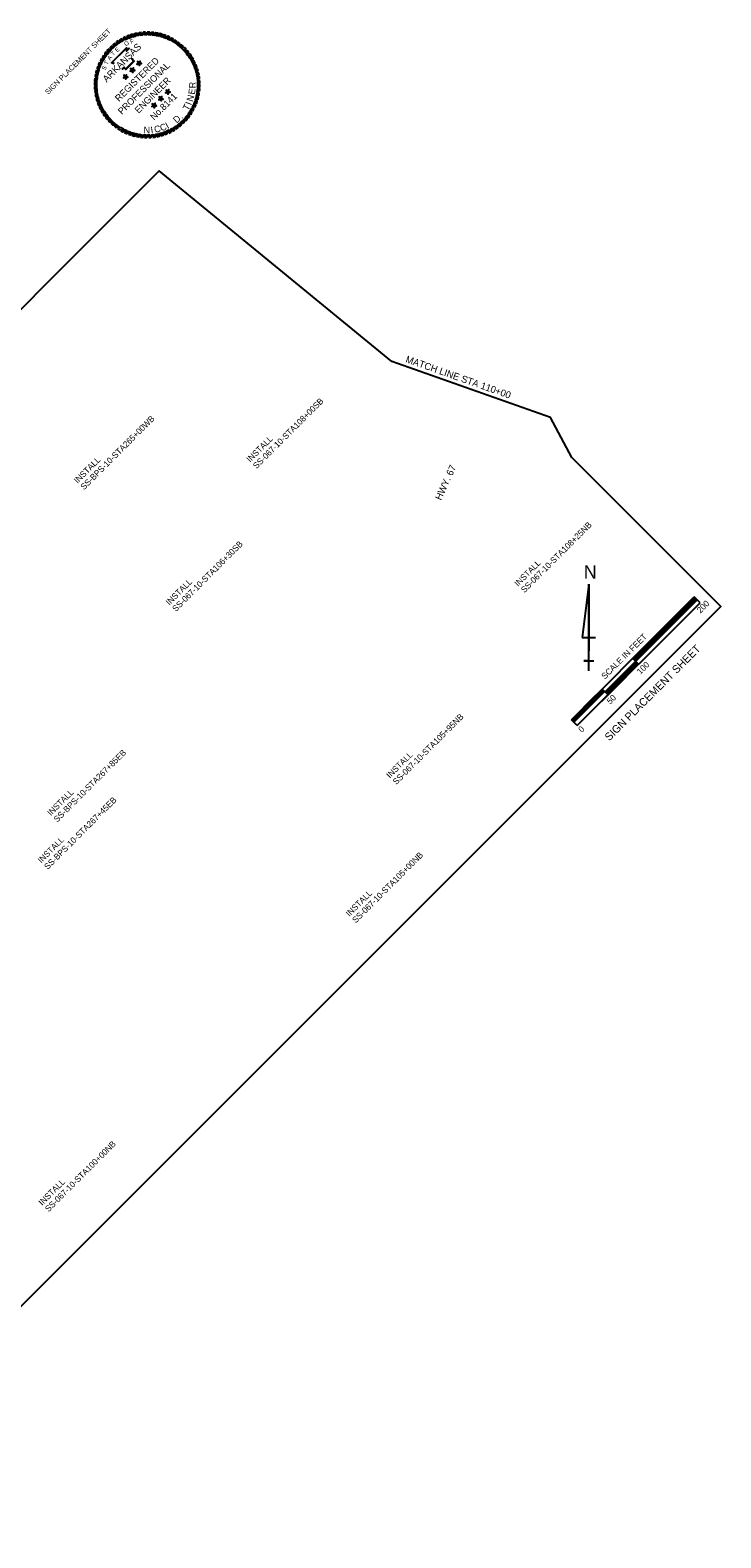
# Model space of a CAD drawing. Extents: x 991038 to 994490, y 1838525 to 1841963.
# Drawn here: x 991998 to 992794, y 1838525 to 1840263 of the extents above; entities that cross this region are included whole.
import ezdxf

# ---------------------------------------------------------------- set-up
doc = ezdxf.new("R2010")
doc.units = 0
for name, color, linetype in [('5', 7, 'Continuous'), ('63', 7, 'Continuous'), ('G-ANNO-SYMB', 7, 'Continuous'), ('G-ANNO-TEXT', 7, 'Continuous'), ('Level 10', 7, 'Continuous'), ('Plan Notes', 7, 'Continuous'), ('R_Annotation', 7, 'Continuous'), ('R_No Plot', 7, 'Continuous')]:
    doc.layers.add(name, color=color, linetype=linetype)

msp = doc.modelspace()

# ---------------------------------------------------------------- linework, layer by layer
at = {"layer": '5'}
msp.add_line((992597.4, 1839816.5), (992414.5, 1839881), dxfattribs=at)
at = {"layer": '63'}
for p, q in [((992641.6, 1839624.4), (992633.9, 1839562.9)), ((992641.6, 1839524.4), (992641.6, 1839624.4)), ((992641.6, 1839624.4), (992641.6, 1839547.5)), ((992633.9, 1839562.9), (992649.2, 1839562.9)), ((992641.6, 1839535.9), (992635.8, 1839535.9)), ((992635.8, 1839535.9), (992647.3, 1839535.9)), ((992641.6, 1839524.4), (992641.6, 1839547.5)), ((992641.6, 1839524.4), (992641.6, 1839535.9))]:
    msp.add_line(p, q, dxfattribs=at)
at = {"layer": 'G-ANNO-SYMB'}
for points in [[(992095.6, 1840247.9), (992093.6, 1840246.3), (992092.7, 1840241.7), (992094.8, 1840243.6)], [(992099.5, 1840250.7), (992097.4, 1840249.2), (992096.1, 1840244.7), (992098.3, 1840246.4)], [(992103.6, 1840253.1), (992101.4, 1840251.8), (992099.7, 1840247.4), (992102.1, 1840249)], [(992107.9, 1840255.2), (992105.5, 1840254.1), (992103.6, 1840249.9), (992106, 1840251.3)], [(992112.3, 1840257), (992109.9, 1840256.1), (992107.6, 1840252), (992110.2, 1840253.2)], [(992116.9, 1840258.4), (992114.4, 1840257.7), (992111.8, 1840253.8), (992114.4, 1840254.8)], [(992121.5, 1840259.5), (992119, 1840259), (992116.1, 1840255.3), (992118.8, 1840256.1)], [(992126.3, 1840260.2), (992123.7, 1840259.9), (992120.5, 1840256.5), (992123.3, 1840257)], [(992131, 1840260.5), (992128.4, 1840260.4), (992125, 1840257.2), (992127.8, 1840257.6)], [(992135.8, 1840260.5), (992133.2, 1840260.5), (992129.5, 1840257.7), (992132.3, 1840257.8)], [(992140.6, 1840260), (992138, 1840260.3), (992134.1, 1840257.8), (992136.9, 1840257.6)], [(992145.3, 1840259.3), (992142.7, 1840259.7), (992138.6, 1840257.5), (992141.4, 1840257.1)], [(992149.9, 1840258.1), (992147.4, 1840258.8), (992143.1, 1840256.8), (992145.9, 1840256.3)], [(992154.4, 1840256.6), (992151.9, 1840257.4), (992147.6, 1840255.8), (992150.3, 1840255.1)], [(992158.8, 1840254.7), (992156.4, 1840255.8), (992151.9, 1840254.5), (992154.6, 1840253.5)], [(992163, 1840252.5), (992160.7, 1840253.7), (992156.2, 1840252.8), (992158.7, 1840251.6)], [(992167.1, 1840249.9), (992164.9, 1840251.4), (992160.3, 1840250.8), (992162.7, 1840249.4)], [(992170.9, 1840247.1), (992168.8, 1840248.7), (992164.2, 1840248.5), (992166.5, 1840246.9)], [(992174.5, 1840244), (992172.6, 1840245.7), (992167.9, 1840245.9), (992170.1, 1840244.1)], [(992080, 1840230), (992078.8, 1840227.7), (992079.7, 1840223.2), (992080.9, 1840225.7)], [(992082.6, 1840234.1), (992081.1, 1840231.9), (992081.7, 1840227.3), (992083.1, 1840229.7)], [(992085.4, 1840237.9), (992083.8, 1840235.8), (992084, 1840231.2), (992085.6, 1840233.5)], [(992088.6, 1840241.5), (992086.8, 1840239.6), (992086.6, 1840234.9), (992088.4, 1840237.1)], [(992092, 1840244.8), (992090.1, 1840243), (992089.5, 1840238.4), (992091.4, 1840240.5)], [(992177.8, 1840240.5), (992176, 1840242.4), (992171.4, 1840243), (992173.5, 1840241.1)], [(992180.9, 1840236.9), (992179.3, 1840238.9), (992174.7, 1840239.8), (992176.6, 1840237.8)], [(992183.7, 1840233), (992182.2, 1840235.1), (992177.7, 1840236.4), (992179.4, 1840234.2)], [(992186.1, 1840228.9), (992184.8, 1840231.2), (992180.4, 1840232.8), (992182, 1840230.4)], [(992188.2, 1840224.6), (992187.1, 1840227), (992182.9, 1840228.9), (992184.3, 1840226.5)], [(992073.3, 1840212.3), (992072.8, 1840209.7), (992075, 1840205.6), (992075.4, 1840208.4)], [(992074.4, 1840216.9), (992073.7, 1840214.4), (992075.7, 1840210.1), (992076.3, 1840212.9)], [(992076, 1840221.4), (992075.1, 1840218.9), (992076.7, 1840214.6), (992077.5, 1840217.3)], [(992077.8, 1840225.8), (992076.8, 1840223.4), (992078, 1840218.9), (992079, 1840221.6)], [(992107.8, 1840209), (992107.6, 1840210.1), (992105.8, 1840211), (992106.7, 1840209.2)], [(992107.8, 1840209), (992108.7, 1840209.5), (992109, 1840211.5), (992107.6, 1840210.1)], [(992115.6, 1840216.9), (992114.6, 1840217), (992113.2, 1840215.6), (992115.2, 1840215.9)], [(992115.6, 1840216.9), (992115.5, 1840217.9), (992113.7, 1840218.8), (992114.6, 1840217)], [(992115.6, 1840216.9), (992115.2, 1840215.9), (992116.1, 1840214.1), (992116.4, 1840216.1)], [(992115.6, 1840216.9), (992116.6, 1840217.4), (992116.9, 1840219.4), (992115.5, 1840217.9)], [(992115.6, 1840216.9), (992116.4, 1840216.1), (992118.4, 1840216.4), (992116.6, 1840217.4)], [(992123.5, 1840224.7), (992122.5, 1840224.9), (992121, 1840223.5), (992123, 1840223.8)], [(992123.5, 1840224.7), (992123.3, 1840225.8), (992121.5, 1840226.7), (992122.5, 1840224.9)], [(992123.5, 1840224.7), (992123, 1840223.8), (992123.9, 1840222), (992124.3, 1840224)], [(992123.5, 1840224.7), (992124.4, 1840225.2), (992124.8, 1840227.2), (992123.3, 1840225.8)], [(992123.5, 1840224.7), (992124.3, 1840224), (992126.2, 1840224.3), (992124.4, 1840225.2)], [(992190, 1840220.2), (992189.1, 1840222.6), (992185, 1840224.9), (992186.2, 1840222.4)], [(992191.4, 1840215.6), (992190.7, 1840218.1), (992186.8, 1840220.7), (992187.8, 1840218.1)], [(992192.5, 1840211), (992192, 1840213.5), (992188.3, 1840216.4), (992189.1, 1840213.7)], [(992193.2, 1840206.3), (992192.9, 1840208.9), (992189.5, 1840212), (992190, 1840209.3)], [(992072, 1840202.8), (992072, 1840200.2), (992074.8, 1840196.5), (992074.7, 1840199.3)], [(992072, 1840198), (992072.1, 1840195.4), (992075.3, 1840192), (992075, 1840194.8)], [(992072.5, 1840207.5), (992072.2, 1840204.9), (992074.8, 1840201.1), (992074.9, 1840203.9)], [(992072.3, 1840193.3), (992072.7, 1840190.7), (992076.1, 1840187.5), (992075.5, 1840190.3)], [(992107.8, 1840209), (992106.7, 1840209.2), (992105.3, 1840207.8), (992107.3, 1840208.1)], [(992107.8, 1840209), (992107.3, 1840208.1), (992108.2, 1840206.3), (992108.5, 1840208.3)], [(992107.8, 1840209), (992108.5, 1840208.3), (992110.5, 1840208.6), (992108.7, 1840209.5)], [(992156.4, 1840191.8), (992156.3, 1840192.9), (992154.5, 1840193.8), (992155.4, 1840192)], [(992156.4, 1840191.8), (992157.4, 1840192.3), (992157.7, 1840194.3), (992156.3, 1840192.9)], [(992192.3, 1840187.3), (992192.7, 1840189.8), (992190.5, 1840193.9), (992190.1, 1840191.1)], [(992193.5, 1840201.5), (992193.4, 1840204.1), (992190.2, 1840207.5), (992190.6, 1840204.7)], [(992193.1, 1840192), (992193.3, 1840194.6), (992190.8, 1840198.5), (992190.6, 1840195.6)], [(992193.5, 1840196.7), (992193.6, 1840199.3), (992190.7, 1840203), (992190.8, 1840200.2)], [(992073, 1840188.5), (992073.6, 1840186), (992077.2, 1840183.1), (992076.5, 1840185.8)], [(992074.1, 1840183.9), (992074.8, 1840181.4), (992078.7, 1840178.8), (992077.7, 1840181.4)], [(992075.5, 1840179.3), (992076.4, 1840176.9), (992080.5, 1840174.6), (992079.3, 1840177.2)], [(992140.7, 1840176.1), (992139.6, 1840176.3), (992138.2, 1840174.8), (992140.2, 1840175.2)], [(992140.7, 1840176.1), (992140.5, 1840177.1), (992138.7, 1840178.1), (992139.6, 1840176.3)], [(992140.7, 1840176.1), (992140.2, 1840175.2), (992141.1, 1840173.4), (992141.4, 1840175.3)], [(992140.7, 1840176.1), (992141.6, 1840176.6), (992142, 1840178.6), (992140.5, 1840177.1)], [(992140.7, 1840176.1), (992141.4, 1840175.3), (992143.4, 1840175.7), (992141.6, 1840176.6)], [(992148.6, 1840184), (992147.5, 1840184.1), (992146.1, 1840182.7), (992148.1, 1840183)], [(992148.6, 1840184), (992148.4, 1840185), (992146.6, 1840185.9), (992147.5, 1840184.1)], [(992148.6, 1840184), (992148.1, 1840183), (992149, 1840181.2), (992149.3, 1840183.2)], [(992148.6, 1840184), (992149.5, 1840184.4), (992149.8, 1840186.4), (992148.4, 1840185)], [(992148.6, 1840184), (992149.3, 1840183.2), (992151.3, 1840183.5), (992149.5, 1840184.4)], [(992156.4, 1840191.8), (992155.4, 1840192), (992153.9, 1840190.6), (992155.9, 1840190.9)], [(992156.4, 1840191.8), (992155.9, 1840190.9), (992156.9, 1840189.1), (992157.2, 1840191.1)], [(992156.4, 1840191.8), (992157.2, 1840191.1), (992159.2, 1840191.4), (992157.4, 1840192.3)], [(992185.5, 1840169.5), (992186.7, 1840171.8), (992185.8, 1840176.4), (992184.6, 1840173.8)], [(992187.7, 1840173.7), (992188.8, 1840176.1), (992187.5, 1840180.6), (992186.5, 1840178)], [(992189.6, 1840178.1), (992190.4, 1840180.6), (992188.9, 1840184.9), (992188.1, 1840182.2)], [(992191.1, 1840182.6), (992191.8, 1840185.2), (992189.8, 1840189.4), (992189.3, 1840186.6)], [(992077.3, 1840174.9), (992078.4, 1840172.5), (992082.6, 1840170.6), (992081.3, 1840173)], [(992079.4, 1840170.6), (992080.7, 1840168.4), (992085.1, 1840166.7), (992083.5, 1840169.1)], [(992081.9, 1840166.5), (992083.3, 1840164.4), (992087.8, 1840163.1), (992086.1, 1840165.3)], [(992084.6, 1840162.6), (992086.3, 1840160.6), (992090.8, 1840159.7), (992088.9, 1840161.8)], [(992087.7, 1840159), (992089.5, 1840157.1), (992094.1, 1840156.5), (992092, 1840158.4)], [(992173.5, 1840154.7), (992175.4, 1840156.5), (992176, 1840161.1), (992174.1, 1840159)], [(992177, 1840158), (992178.7, 1840160), (992178.9, 1840164.6), (992177.1, 1840162.4)], [(992180.1, 1840161.6), (992181.7, 1840163.7), (992181.5, 1840168.3), (992179.9, 1840166)], [(992182.9, 1840165.4), (992184.4, 1840167.6), (992183.8, 1840172.3), (992182.4, 1840169.8)], [(992091, 1840155.6), (992093, 1840153.8), (992097.6, 1840153.6), (992095.4, 1840155.4)], [(992094.6, 1840152.4), (992096.7, 1840150.8), (992101.3, 1840151), (992099, 1840152.6)], [(992098.4, 1840149.6), (992100.6, 1840148.1), (992105.3, 1840148.7), (992102.8, 1840150.1)], [(992102.5, 1840147), (992104.8, 1840145.8), (992109.4, 1840146.7), (992106.8, 1840147.9)], [(992106.7, 1840144.8), (992109.1, 1840143.8), (992113.6, 1840145), (992111, 1840146)], [(992111.1, 1840143), (992113.6, 1840142.1), (992118, 1840143.7), (992115.2, 1840144.5)], [(992115.6, 1840141.4), (992118.2, 1840140.7), (992122.4, 1840142.7), (992119.6, 1840143.2)], [(992120.3, 1840140.3), (992122.8, 1840139.8), (992126.9, 1840142), (992124.1, 1840142.4)], [(992125, 1840139.5), (992127.6, 1840139.2), (992131.5, 1840141.8), (992128.6, 1840141.9)], [(992129.7, 1840139), (992132.3, 1840139), (992136, 1840141.8), (992133.2, 1840141.7)], [(992134.5, 1840139), (992137.1, 1840139.1), (992140.5, 1840142.3), (992137.7, 1840142)], [(992139.3, 1840139.3), (992141.9, 1840139.6), (992145, 1840143.1), (992142.3, 1840142.5)], [(992144, 1840140), (992146.5, 1840140.5), (992149.4, 1840144.2), (992146.7, 1840143.4)], [(992148.6, 1840141.1), (992151.1, 1840141.8), (992153.7, 1840145.7), (992151.1, 1840144.7)], [(992153.2, 1840142.5), (992155.6, 1840143.4), (992157.9, 1840147.5), (992155.4, 1840146.3)], [(992157.6, 1840144.3), (992160, 1840145.4), (992162, 1840149.6), (992159.5, 1840148.3)], [(992161.9, 1840146.4), (992164.2, 1840147.7), (992165.8, 1840152.1), (992163.4, 1840150.5)], [(992166, 1840148.9), (992168.2, 1840150.3), (992169.4, 1840154.8), (992167.2, 1840153.1)], [(992169.9, 1840151.6), (992171.9, 1840153.3), (992172.8, 1840157.8), (992170.8, 1840155.9)]]:
    msp.add_lwpolyline(points, close=True, dxfattribs=at)
for points in [[(992094.7, 1840224.1), (992091.5, 1840225.2), (992108.8, 1840242.6), (992109.2, 1840239.3), (992110.4, 1840240.5), (992111.3, 1840241.5), (992112.4, 1840242.4)], [(992094.8, 1840224.4), (992092.2, 1840225.4), (992108.5, 1840241.7), (992108.9, 1840238.5), (992110.6, 1840240.2), (992111.6, 1840241.2), (992112.7, 1840242.1)], [(992115.5, 1840230.4), (992115.5, 1840229.9), (992115.8, 1840229.4), (992116.6, 1840228.4), (992117.8, 1840227.2), (992108.1, 1840217.5), (992106.5, 1840219.2), (992106.1, 1840219.5), (992105.6, 1840219.2), (992104.2, 1840217.9), (992103.6, 1840218)], [(992115.2, 1840230.4), (992115.1, 1840229.8), (992115.4, 1840229.2), (992116.3, 1840228.2), (992117.2, 1840227.2), (992108.1, 1840218.1), (992106.7, 1840219.4), (992106.2, 1840220), (992105.3, 1840219.6), (992104.1, 1840218.3), (992103.7, 1840218.4)]]:
    msp.add_lwpolyline(points, dxfattribs=at)
at = {"layer": 'Level 10'}
for p, q in [((992628.4, 1839461.4), (992769.8, 1839602.8)), ((992678.2, 1839524.8), (992763, 1839609.6)), ((992692.9, 1839538.3), (992763.6, 1839609)), ((992693.5, 1839537.8), (992764.2, 1839608.5)), ((992694, 1839537.2), (992764.7, 1839607.9)), ((992694.6, 1839536.6), (992765.3, 1839607.4)), ((992695.2, 1839536.1), (992765.9, 1839606.8)), ((992695.7, 1839535.5), (992766.4, 1839606.2)), ((992769.8, 1839602.8), (992763.1, 1839609.6)), ((992621.6, 1839468.2), (992734.8, 1839581.3)), ((992695.7, 1839535.5), (992738.1, 1839577.9)), ((992660.4, 1839500.2), (992695.7, 1839535.5)), ((992660.9, 1839499.6), (992696.3, 1839534.9)), ((992661.5, 1839499), (992696.9, 1839534.4)), ((992662.1, 1839498.5), (992697.4, 1839533.8)), ((992662.6, 1839497.9), (992698, 1839533.2)), ((992663.2, 1839497.3), (992698.6, 1839532.7)), ((992699.1, 1839532.1), (992692.3, 1839538.9)), ((992656.7, 1839489.7), (992685, 1839518)), ((992622.2, 1839467.6), (992657.5, 1839503)), ((992622.7, 1839467.1), (992658.1, 1839502.4)), ((992623.3, 1839466.5), (992658.7, 1839501.9)), ((992623.9, 1839465.9), (992659.2, 1839501.3)), ((992624.4, 1839465.4), (992659.8, 1839500.7)), ((992663.8, 1839496.8), (992657, 1839503.5)), ((992621.6, 1839468.2), (992649.9, 1839496.5)), ((992628.4, 1839461.4), (992621.6, 1839468.2))]:
    msp.add_line(p, q, dxfattribs=at)
at = {"layer": 'R_No Plot'}
msp.add_lwpolyline([(991037.8, 1839207.9), (991720.4, 1838525.3), (992793.8, 1839598.7), (992622.1, 1839770.3), (992597.4, 1839816.5), (992414.5, 1839881), (992146.5, 1840100.7), (991858.2, 1839812.3), (991737.8, 1839932.6), (991499.1, 1839706.6), (991537.9, 1839516.5), (991253, 1839231.6)], close=True, dxfattribs=at)

# ---------------------------------------------------------------- texts
at = {"layer": '63'}
msp.add_text('N', height=15.4, rotation=360, dxfattribs=at).set_placement((992635.9, 1839630.8))
at = {"layer": 'G-ANNO-SYMB'}
for s, height, rotation, p in [('ARKANSAS', 7.89, 45, (992086.1, 1840202.3)), ('O', 4.84, 26.2218, (992107.7, 1840244.2)), ('F', 4.84, 20.3628, (992114.1, 1840247)), ('T', 4.84, 61.9015, (992086.9, 1840222.5)), ('A', 4.84, 53.6788, (992090, 1840227.7)), ('T', 4.84, 46.4789, (992093.7, 1840232.8)), ('E', 4.84, 41.672, (992098.2, 1840237.1)), ('REGISTERED', 7.64, 45, (992100.3, 1840180)), ('S', 4.84, 64.7726, (992084.5, 1840216.2)), ('PROFESSIONAL', 7.642, 45, (992103.6, 1840165.1)), ('ENGINEER', 7.64, 45, (992122.9, 1840166.4)), ('E', 7.64, 82.6498, (992187.7, 1840188.3)), ('R', 7.64, 90.478, (992188.7, 1840195.9)), ('No.8141', 7.61, 45, (992140.8, 1840158.6)), ('T', 7.64, 61.7747, (992180, 1840169.5)), ('I', 7.64, 69.2301, (992183.5, 1840175.8)), ('N', 7.64, 73.7033, (992185.2, 1840179.9)), ('D', 7.64, 41.6451, (992166.7, 1840155.1)), ('.', 7.64, 49.846, (992172.7, 1840160.3)), ('N', 7.64, 0.2676, (992128.7, 1840143.8)), ('I', 7.64, 9.2141, (992137.4, 1840143.8)), ('C', 7.64, 13.6873, (992141.8, 1840144.4)), ('C', 7.64, 21.5155, (992149.2, 1840146.1)), ('I', 7.64, 29.3437, (992156.4, 1840148.9))]:
    msp.add_text(s, height=height, rotation=rotation, dxfattribs=at).set_placement(p)
at = {"layer": 'G-ANNO-TEXT'}
for height, p in [(6, (992018.6, 1840188.1)), (9, (992665.3, 1839443.1))]:
    msp.add_text('SIGN PLACEMENT SHEET', height=height, rotation=45, dxfattribs=at).set_placement(p)
at = {"layer": 'Level 10'}
for s, height, p in [('200', 7, (992770.2, 1839590.4)), ('SCALE IN FEET', 7.001, (992660.3, 1839514.3)), ('100', 7, (992701.1, 1839519.8)), ('50', 7, (992666.4, 1839485.5)), ('0', 7, (992633.6, 1839453))]:
    msp.add_text(s, height=height, rotation=45.0003, dxfattribs=at).set_placement(p)
at = {"layer": 'Plan Notes'}
for s, rotation, p in [('MATCH LINE STA 110+00', 340.5626, (992429.9, 1839880.4)), ('HWY. 67', 65.5306, (992471.4, 1839720.4))]:
    msp.add_text(s, height=8, rotation=rotation, dxfattribs=at).set_placement(p)
at = {"layer": 'R_Annotation'}
for s, p in [('SS-067-10-STA108+00SB', (992258.8, 1839756.8)), ('SS-BPS-10-STA265+00WB', (992060.1, 1839732.5)), ('INSTALL', (992251.4, 1839764.3)), ('INSTALL', (992052.7, 1839740)), ('SS-067-10-STA108+25NB', (992567.5, 1839613.8)), ('SS-067-10-STA106+30SB', (992165.8, 1839592.1)), ('INSTALL', (992560.1, 1839621.2)), ('INSTALL', (992158.4, 1839599.5)), ('SS-067-10-STA105+95NB', (992419.9, 1839392.7)), ('SS-BPS-10-STA267+85EB', (992029.2, 1839349.5)), ('INSTALL', (992412.5, 1839400.2)), ('SS-BPS-10-STA267+45EB', (992018.2, 1839294.9)), ('INSTALL', (992021.8, 1839356.9)), ('INSTALL', (992010.8, 1839302.3)), ('SS-067-10-STA105+00NB', (992373.2, 1839233.3)), ('INSTALL', (992365.8, 1839240.7)), ('SS-067-10-STA100+00NB', (992019.2, 1838900.4)), ('INSTALL', (992011.8, 1838907.8))]:
    msp.add_text(s, height=7, rotation=45, dxfattribs=at).set_placement(p)

doc.saveas('drawing.dxf')
